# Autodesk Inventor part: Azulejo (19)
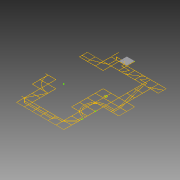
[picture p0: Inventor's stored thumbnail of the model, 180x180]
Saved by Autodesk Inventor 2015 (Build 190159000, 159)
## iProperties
Created: 2015-04
Part Number: Azulejo (19)
Material: Genérico
Document SubType Name: Modeling
Designer: Felipe
Density: 1 g/cm^3
Appearance: Padrão
Author: Felipe
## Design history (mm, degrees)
sketch "Sketch1"
  geometry: L1 (-1510, -7490)-(-1510, -6010); L2 (992.445, 7510)-(992.445, 8990); L3 (1012.445, 7510)-(1012.445, 8990); L4 (-3010, -1490)-(-3010, -10); L5 (-1510, 7490)-(-2990, 7490); L6 (-2990, 10)-(-1510, 10); L7 (-1510, -10)-(-2990, -10); L8 (-1510, -1490)-(-1510, -10); L9 (-10, 9010)-(-10, 10490); L10 (-10, 7510)-(-10, 8990); L11 (-10, 7490)-(-1490, 7490); L12 (-1490, 6010)-(-10, 6010); L13 (-10, 5990)-(-1490, 5990); L14 (-1490, -10)-(-1490, -1490); L15 (-1490, -1490)-(-10, -1490); L16 (-10, -1510)-(-1490, -1510); L17 (-10, -2990)-(-10, -1510); L18 (-10, -5990)-(-10, -4510); L19 (-1490, -7490)-(-10, -7490); L20 (10, 8990)-(10, 7510); L21 (1490, 7510)-(1490, 8990); L22 (10, 6010)-(1490, 6010); L23 (1490, 6010)-(1490, 7490); L24 (1490, 5990)-(10, 5990); L25 (4490, -6010)-(3010, -6010); L26 (10, -1510)-(10, -2990); L27 (10, -3010)-(10, -4490); L28 (10, -4510)-(10, -5990); L29 (10, -5990)-(1490, -5990); L30 (1490, -6010)-(10, -6010); L31 (10, -7490)-(1490, -7490); L32 (2990, 9010)-(2990, 10490); L33 (1510, 8990)-(1510, 7510); L34 (1510, 7510)-(2990, 7510); L35 (2990, 7490)-(1510, 7490); L36 (1510, 7490)-(1510, 6010); L37 (1510, -5990)-(2990, -5990); L38 (2990, -6010)-(1510, -6010); L39 (1510, -7490)-(2990, -7490); L40 (3010, 10490)-(3010, 9010); L41 (3010, 9010)-(4490, 9010); L42 (4490, 8990)-(3010, 8990); L43 (4490, 7490)-(3010, 7490); L44 (4490, 1510)-(4490, 2990); L45 (4490, 10)-(4490, 1490); L46 (4490, -1490)-(4490, -10); L47 (4490, -2990)-(4490, -1510); L48 (3010, -5990)-(4490, -5990); L49 (3010, -7490)-(4490, -7490); L50 (4510, 9010)-(5990, 9010); L51 (5990, 8990)-(4510, 8990); L52 (4510, 7510)-(5990, 7510); L53 (5990, 7490)-(4510, 7490); L54 (4510, 3010)-(5990, 3010); L55 (5990, 2990)-(4510, 2990); L56 (4510, 2990)-(4510, 1510); L57 (4510, 1510)-(5990, 1510); L58 (5990, 1510)-(5990, 1740.185); L59 (5990, 1760.2)-(5990, 2259.8); L60 (5990, 2279.815)-(5990, 2990); L61 (5990, 1490)-(4510, 1490); L62 (4510, 1490)-(4510, 10); L63 (4510, 10)-(5990, 10); L64 (5990, 10)-(5990, 1490)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; A1 r 250 centre (6000, 2010) between (5990, 2259.8) and (5990, 1760.2); A2 r 250 centre (6000, 2010) between (6010, 1760.2) and (6010, 2259.8); A3 r 270 centre (6000, 2010) between (5990, 2279.815) and (5990, 1740.185); A4 r 270 centre (6000, 2010) between (6010, 1740.185) and (6010, 2279.815); A5 r 3010.017 centre (0, 0) between (-1490, -2615.358) and (-346.554, -2990); A6 r 2990.017 centre (0, 0) between (-1490, -2592.316) and (-10, -2990); A7 r 3010.017 centre (0, 0) between (-2603.863, -1510) and (-1510, -2603.863); A8 r 2990.017 centre (0, 0) between (-2580.717, -1510) and (-1510, -2580.717); A9 r 3010.017 centre (0, 0) between (-2990, -346.554) and (-2615.358, -1490); A10 r 2990.017 centre (0, 0) between (-2990, -10) and (-2592.316, -1490); A11 r 2131.367 centre (7500, -1500) between (7490, 631.344) and (6010, 24.017); A12 r 2131.367 centre (7500, -1500) between (5975.983, -10) and (5368.656, -1490); A13 r 2131.367 centre (7500, -1500) between (5368.656, -1510) and (5975.983, -2990); A14 r 2131.367 centre (7500, -1500) between (6010, -3024.017) and (7190, -3608.703); A15 r 1831.367 centre (7500, -1500) between (7490.321, 331.342) and (6463.753, 10); A16 r 1831.367 centre (7500, -1500) between (6435.196, -10) and (6010, -435.196); A17 r 1831.367 centre (7500, -1500) between (5990, -463.753) and (5668.66, -1490); A18 r 1831.367 centre (7500, -1500) between (5668.66, -1510) and (5990, -2536.247); A19 r 1831.367 centre (7500, -1500) between (6010, -2564.804) and (6435.196, -2990); A20 r 1831.367 centre (7500, -1500) between (6463.753, -3010) and (7490, -3331.34); A21 r 2111.367 centre (7500, -1500) between (7490.047, 611.344) and (6024.272, 10); A22 r 2111.367 centre (7500, -1500) between (5990, -24.272) and (5388.656, -1490); A23 r 2111.367 centre (7500, -1500) between (5388.656, -1510) and (5990, -2975.728); A24 r 2111.367 centre (7500, -1500) between (6024.272, -3010) and (7210, -3591.357); A25 r 1811.367 centre (7500, -1500) between (7490.374, 311.342) and (6499.524, 10); A26 r 1811.367 centre (7500, -1500) between (6469.975, -10) and (6010, -469.975); A27 r 1811.367 centre (7500, -1500) between (5990, -499.524) and (5688.66, -1490); A28 r 1811.367 centre (7500, -1500) between (5688.66, -1510) and (5990, -2500.476); A29 r 1811.367 centre (7500, -1500) between (6010, -2530.025) and (6469.975, -2990); A30 r 1811.367 centre (7500, -1500) between (6499.524, -3010) and (7490, -3311.34); A31 r 449.871 centre (7499.449, -4060.672) between (7510, -4510.419) and (7521.546, -4510); 4 further points
  constraints: 1042 end point, 64 point on circle, 31 centre point, 13 point on line, 1 horizontal, 1 other
extrude "Extrusion1" new body sketch "Sketch1" distance "d0" = 60; taper "d1" = 0 deg
extrude "Extrusion2" new body sketch "Sketch1" distance "d2" = 60; taper "d3" = 0 deg
body "Solid1"
body "Solid2"
